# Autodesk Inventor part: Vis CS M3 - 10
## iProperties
Shininess: 64.0
Length Units: 11269
Angle Units: 11279
Time Units: 11290
Mass Units: 11283
Length Display Precision: 3
Angle Display Precision: 2
Compacted: True
Part Number: Vis CS M3 - 10
Document SubType Name: Modeling
Created: 2006-01
Material: Par défaut
Designer: Fricot
Density: 0.0
Volumn: 0.0
Area: 0.0
PropertySet Name: Model Information
Control State: 0
Master: False
Checked Out: False
Author: Fricot
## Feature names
1. Base1
